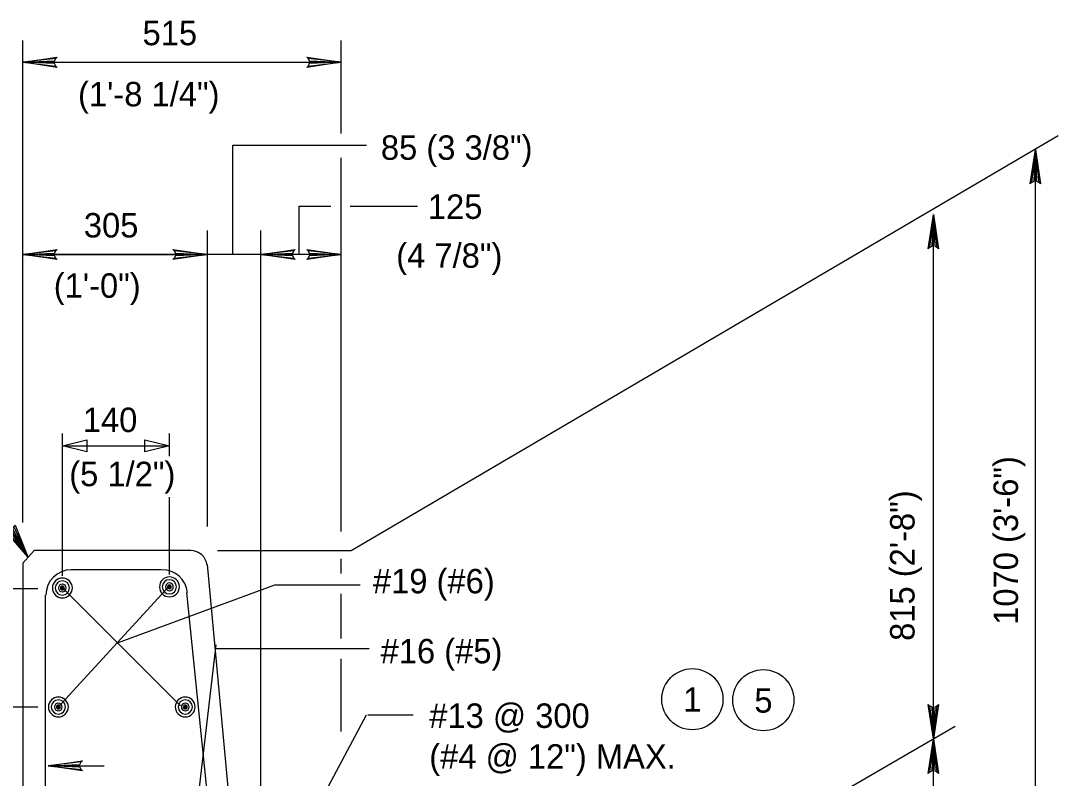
# Model space of a CAD drawing. Extents: x 652000 to 652262, y 303155 to 303399.
# Drawn here: x 652090.8 to 652218.1, y 303306 to 303398.9 of the extents above; entities that cross this region are included whole.
import ezdxf

# ---------------------------------------------------------------- set-up
doc = ezdxf.new("R2010")
doc.units = 0
doc.layers.add('2', color=7, linetype='Continuous')

msp = doc.modelspace()

# ---------------------------------------------------------------- linework, layer by layer
at = {"layer": '2'}
for p, q in [((652091.07, 303368.98), (652091.07, 303396.5)), ((652130.13, 303385.09), (652130.13, 303396.5)), ((652091.07, 303393.84), (652130.13, 303393.84)), ((652131.38, 303333.92), (652218.1, 303384.86)), ((652116.85, 303370.25), (652116.85, 303383.68)), ((652116.85, 303383.68), (652133.25, 303383.68)), ((652215.29, 303297.83), (652215.29, 303383.14)), ((652130.13, 303336.27), (652130.13, 303382.12)), ((652124.97, 303370.25), (652124.97, 303376.18)), ((652124.97, 303376.18), (652128.88, 303376.18)), ((652131.22, 303376.18), (652139.5, 303376.18)), ((652202.79, 303310.8), (652202.79, 303375.17)), ((652113.72, 303369.04), (652113.72, 303373.21)), ((652120.29, 303292.52), (652120.29, 303373.21)), ((652091.07, 303370.25), (652113.72, 303370.25)), ((652120.29, 303370.25), (652091.07, 303370.25)), ((652130.13, 303370.25), (652120.29, 303370.25)), ((652091.07, 303337.36), (652091.07, 303368.98)), ((652113.72, 303336.89), (652113.72, 303369.04)), ((652091.69, 303333.14), (652078.56, 303354.7)), ((652095.94, 303330.83), (652095.94, 303348.27)), ((652109.07, 303345.5), (652109.07, 303348.27)), ((652095.94, 303346.77), (652109.07, 303346.77)), ((652109.07, 303330.97), (652109.07, 303340.48)), ((652092.47, 303333.92), (652091.07, 303332.36)), ((652111.69, 303333.92), (652092.47, 303333.92)), ((652114.97, 303333.92), (652131.38, 303333.92)), ((652130.13, 303331.11), (652130.13, 303332.91)), ((652091.07, 303332.36), (652091.07, 303294.75)), ((652097, 303331.58), (652108.1, 303331.58)), ((652119.19, 303273.3), (652113.72, 303332.21)), ((652092.94, 303329.24), (652079.66, 303329.24)), ((652095.44, 303314.71), (652109.04, 303329.55)), ((652095.91, 303329.39), (652110.44, 303314.86)), ((652102.69, 303322.62), (652122, 303329.71)), ((652118.18, 303259.85), (652111.22, 303328.77)), ((652122, 303329.71), (652132.47, 303329.71)), ((652093.88, 303290.8), (652093.88, 303328.46)), ((652130.13, 303323.14), (652130.13, 303328.61)), ((652111.07, 303290.33), (652114.82, 303322.36)), ((652114.66, 303321.89), (652133.57, 303321.89)), ((652130.13, 303311.74), (652130.13, 303320.64)), ((652092.94, 303314.71), (652079.66, 303314.71)), ((652113.1, 303276.11), (652133.25, 303313.77)), ((652133.41, 303313.77), (652138.98, 303313.77)), ((652129.82, 303268.61), (652205.44, 303312.36)), ((652202.79, 303295.02), (652202.79, 303310.8)), ((652094.19, 303307.52), (652101.07, 303307.52))]:
    msp.add_line(p, q, dxfattribs=at)
for points in [[(652095.13, 303393.37), (652094.97, 303393.68), (652091.07, 303393.84), (652095.13, 303393.37), (652095.29, 303393.21), (652091.07, 303393.84), (652094.97, 303394), (652095.13, 303394.31), (652091.07, 303393.84), (652095.29, 303394.46), (652095.13, 303394.31)], [(652095.13, 303393.37), (652094.97, 303393.68), (652091.07, 303393.84), (652095.13, 303393.37), (652095.29, 303393.21), (652091.07, 303393.84), (652094.97, 303394), (652095.13, 303394.31), (652091.07, 303393.84), (652095.29, 303394.46), (652095.13, 303394.31)], [(652126.07, 303394.31), (652126.22, 303394), (652130.13, 303393.84), (652126.07, 303394.31), (652125.91, 303394.46), (652130.13, 303393.84), (652126.22, 303393.68), (652126.07, 303393.37), (652130.13, 303393.84), (652125.91, 303393.21), (652126.07, 303393.37)], [(652126.07, 303394.31), (652126.22, 303394), (652130.13, 303393.84), (652126.07, 303394.31), (652125.91, 303394.46), (652130.13, 303393.84), (652126.22, 303393.68), (652126.07, 303393.37), (652130.13, 303393.84), (652125.91, 303393.21), (652126.07, 303393.37)], [(652214.82, 303379.08), (652215.13, 303379.24), (652215.29, 303383.14), (652214.82, 303379.08), (652214.66, 303378.92), (652215.29, 303383.14), (652215.44, 303379.24), (652215.75, 303379.08), (652215.29, 303383.14), (652215.91, 303378.92), (652215.75, 303379.08)], [(652202.32, 303371.11), (652202.63, 303371.27), (652202.79, 303375.17), (652202.32, 303371.11), (652202.16, 303370.96), (652202.79, 303375.17), (652202.94, 303371.27), (652203.25, 303371.11), (652202.79, 303375.17), (652203.41, 303370.96), (652203.25, 303371.11)], [(652095.13, 303369.78), (652094.97, 303370.09), (652091.07, 303370.25), (652095.13, 303369.78), (652095.29, 303369.62), (652091.07, 303370.25), (652094.97, 303370.4), (652095.13, 303370.71), (652091.07, 303370.25), (652095.29, 303370.87), (652095.13, 303370.71)], [(652095.13, 303369.78), (652094.97, 303370.09), (652091.07, 303370.25), (652095.13, 303369.78), (652095.29, 303369.62), (652091.07, 303370.25), (652094.97, 303370.4), (652095.13, 303370.71), (652091.07, 303370.25), (652095.29, 303370.87), (652095.13, 303370.71)], [(652109.66, 303370.71), (652109.82, 303370.4), (652113.72, 303370.25), (652109.66, 303370.71), (652109.5, 303370.87), (652113.72, 303370.25), (652109.82, 303370.09), (652109.66, 303369.78), (652113.72, 303370.25), (652109.5, 303369.62), (652109.66, 303369.78)], [(652109.66, 303370.71), (652109.82, 303370.4), (652113.72, 303370.25), (652109.66, 303370.71), (652109.5, 303370.87), (652113.72, 303370.25), (652109.82, 303370.09), (652109.66, 303369.78), (652113.72, 303370.25), (652109.5, 303369.62), (652109.66, 303369.78)], [(652124.35, 303369.78), (652124.19, 303370.09), (652120.29, 303370.25), (652124.35, 303369.78), (652124.5, 303369.62), (652120.29, 303370.25), (652124.19, 303370.4), (652124.35, 303370.71), (652120.29, 303370.25), (652124.5, 303370.87), (652124.35, 303370.71)], [(652124.35, 303369.78), (652124.19, 303370.09), (652120.29, 303370.25), (652124.35, 303369.78), (652124.5, 303369.62), (652120.29, 303370.25), (652124.19, 303370.4), (652124.35, 303370.71), (652120.29, 303370.25), (652124.5, 303370.87), (652124.35, 303370.71)], [(652126.07, 303370.71), (652126.22, 303370.4), (652130.13, 303370.25), (652126.07, 303370.71), (652125.91, 303370.87), (652130.13, 303370.25), (652126.22, 303370.09), (652126.07, 303369.78), (652130.13, 303370.25), (652125.91, 303369.62), (652126.07, 303369.78)], [(652089.97, 303336.89), (652089.82, 303336.58), (652091.69, 303333.14), (652089.97, 303336.89), (652090.13, 303337.05), (652091.69, 303333.14), (652089.5, 303336.42), (652089.19, 303336.27), (652091.69, 303333.14), (652088.88, 303336.42), (652089.19, 303336.27)], [(652203.25, 303314.86), (652202.94, 303314.71), (652202.79, 303310.8), (652203.25, 303314.86), (652203.41, 303315.02), (652202.79, 303310.8), (652202.63, 303314.71), (652202.32, 303314.86), (652202.79, 303310.8), (652202.16, 303315.02), (652202.32, 303314.86)], [(652203.25, 303314.86), (652202.94, 303314.71), (652202.79, 303310.8), (652203.25, 303314.86), (652203.41, 303315.02), (652202.79, 303310.8), (652202.63, 303314.71), (652202.32, 303314.86), (652202.79, 303310.8), (652202.16, 303315.02), (652202.32, 303314.86)], [(652202.32, 303306.74), (652202.63, 303306.89), (652202.79, 303310.8), (652202.32, 303306.74), (652202.16, 303306.58), (652202.79, 303310.8), (652202.94, 303306.89), (652203.25, 303306.74), (652202.79, 303310.8), (652203.41, 303306.58), (652203.25, 303306.74)], [(652202.32, 303306.74), (652202.63, 303306.89), (652202.79, 303310.8), (652202.32, 303306.74), (652202.16, 303306.58), (652202.79, 303310.8), (652202.94, 303306.89), (652203.25, 303306.74), (652202.79, 303310.8), (652203.41, 303306.58), (652203.25, 303306.74)], [(652098.25, 303307.05), (652098.1, 303307.36), (652094.19, 303307.52), (652098.25, 303307.05), (652098.41, 303306.89), (652094.19, 303307.52), (652098.1, 303307.67), (652098.25, 303307.99), (652094.19, 303307.52), (652098.41, 303308.14), (652098.25, 303307.99)], [(652098.25, 303307.05), (652098.1, 303307.36), (652094.19, 303307.52), (652098.25, 303307.05), (652098.41, 303306.89), (652094.19, 303307.52), (652098.1, 303307.67), (652098.25, 303307.99), (652094.19, 303307.52), (652098.41, 303308.14), (652098.25, 303307.99)]]:
    msp.add_lwpolyline(points, dxfattribs=at)
for points in [[(652098.94, 303346.02), (652095.94, 303346.77), (652098.94, 303347.52)], [(652106.07, 303347.52), (652109.07, 303346.77), (652106.07, 303346.02)]]:
    msp.add_lwpolyline(points, close=True, dxfattribs=at)
for centre in [(652173.22, 303315.68), (652181.92, 303315.56)]:
    msp.add_circle(centre, 3.75, dxfattribs=at)
for centre, radius, start, end in [((652111.71, 303331.93), 1.98, 6.0088, 89.9998), ((652097.04, 303328.45), 3.12, 90, 180), ((652108.18, 303328.45), 3.12, 5.8377, 90), ((652095.94, 303329.33), 1.22, 0, 180), ((652095.94, 303329.33), 0.873, 0, 180), ((652109.07, 303329.47), 1.22, 0, 180), ((652109.07, 303329.47), 0.873, 0, 180), ((652095.94, 303329.33), 1.22, 180, 0), ((652095.94, 303329.33), 0.873, 180, 0), ((652095.94, 303329.33), 0.478, 0, 180), ((652095.94, 303329.33), 0.478, 180, 0), ((652095.94, 303329.33), 0.241, 0, 180), ((652095.94, 303329.33), 0.241, 180, 0), ((652095.94, 303329.33), 0.103, 0, 180), ((652095.94, 303329.33), 0.103, 180, 0), ((652109.07, 303329.47), 1.22, 180, 0), ((652109.07, 303329.47), 0.873, 180, 0), ((652109.07, 303329.47), 0.478, 0, 180), ((652109.07, 303329.47), 0.478, 180, 0), ((652109.07, 303329.47), 0.241, 0, 180), ((652109.07, 303329.47), 0.241, 180, 0), ((652109.07, 303329.47), 0.103, 0, 180), ((652109.07, 303329.47), 0.103, 180, 0), ((652095.45, 303314.73), 1.22, 0, 180), ((652095.45, 303314.73), 1.22, 180, 0), ((652095.45, 303314.73), 0.873, 0, 180), ((652095.45, 303314.73), 0.873, 180, 0), ((652095.45, 303314.73), 0.478, 0, 180), ((652095.45, 303314.73), 0.478, 180, 0), ((652095.45, 303314.73), 0.241, 0, 180), ((652095.45, 303314.73), 0.241, 180, 0), ((652095.45, 303314.73), 0.103, 0, 180), ((652095.45, 303314.73), 0.103, 180, 0), ((652111.01, 303314.73), 1.22, 0, 180), ((652111.01, 303314.73), 1.22, 180, 0), ((652111.01, 303314.73), 0.873, 0, 180), ((652111.01, 303314.73), 0.873, 180, 0), ((652111.01, 303314.73), 0.478, 0, 180), ((652111.01, 303314.73), 0.478, 180, 0), ((652111.01, 303314.73), 0.241, 0, 180), ((652111.01, 303314.73), 0.241, 180, 0), ((652111.01, 303314.73), 0.103, 0, 180), ((652111.01, 303314.73), 0.103, 180, 0)]:
    msp.add_arc(centre, radius, start, end, dxfattribs=at)

# ---------------------------------------------------------------- texts
for s, p in [('515', (652105.77, 303395.93)), ('(1\'-8 1/4")', (652097.86, 303388.43)), ('85 (3 3/8")', (652135.01, 303381.87)), ('125', (652140.77, 303374.62)), ('305', (652098.57, 303372.34)), ('(4 7/8")', (652136.89, 303368.62)), ('(1\'-0")', (652094.88, 303364.94)), ('140', (652098.44, 303348.46)), ('(5 1/2")', (652096.78, 303341.82)), ('#19 (#6)', (652134.03, 303328.67)), ('#16 (#5)', (652134.97, 303320.08)), ('1', (652172.1, 303314.15)), ('5', (652180.82, 303314.03)), ('#13 @ 300', (652140.94, 303312.16)), ('(#4 @ 12") MAX.', (652140.94, 303307.16))]:
    msp.add_text(s, height=3, dxfattribs=at).set_placement(p)
for s, p in [('1070 (3\'-6")', (652213.16, 303324.81)), ('815 (2\'-8")', (652200.47, 303322.84))]:
    msp.add_text(s, height=3, rotation=90, dxfattribs=at).set_placement(p)

doc.saveas('drawing.dxf')
